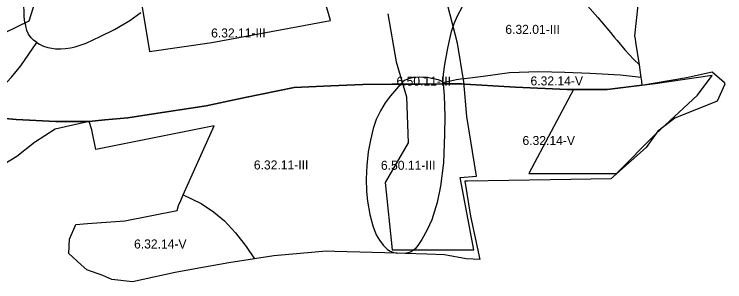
# Model space of a CAD drawing. Extents: x -555156 to -540209, y -1046851 to -1035695.
# Drawn here: x -542138 to -541353, y -1041203 to -1040907 of the extents above; entities that cross this region are included whole.
import ezdxf

# ---------------------------------------------------------------- set-up
doc = ezdxf.new("R2010")
doc.units = 0
for name, color, linetype in [('Vrstva 27', 7, 'Continuous'), ('Vrstva 28', 7, 'Continuous'), ('Vrstva 29', 7, 'Continuous')]:
    doc.layers.add(name, color=color, linetype=linetype)

msp = doc.modelspace()

# ---------------------------------------------------------------- linework, layer by layer
at = {"layer": 'Vrstva 28'}
for points in [[(-541451.53, -1040937.71), (-541452.1, -1040933.94), (-541452.57, -1040930.82), (-541447.15, -1040879.66), (-541446.57, -1040874.15), (-541476.12, -1040864.59), (-541481.08, -1040858.73), (-541481.64, -1040855.4), (-541482.26, -1040855.37), (-541485.3, -1040855.23), (-541482.64, -1040849.4), (-541483.84, -1040842.23), (-541503.49, -1040823.59)], [(-541568.84, -1040841.7), (-541562.46, -1040846.98), (-541560.17, -1040848.87), (-541557.04, -1040851.31), (-541548.08, -1040858.29), (-541535.08, -1040868.45), (-541523.28, -1040878.31), (-541520.69, -1040880.83), (-541512.08, -1040889.22), (-541505.13, -1040897.44), (-541493.63, -1040910.44), (-541479.44, -1040927.18), (-541475.39, -1040932.07), (-541472.3, -1040935.8), (-541463.64, -1040946.24), (-541454.38, -1040956.55), (-541447.73, -1040962.91)], [(-542113.35, -1040938.19), (-542117.02, -1040935.55), (-542119.58, -1040932.81), (-542122.48, -1040928.71), (-542124.27, -1040924.87), (-542125.49, -1040919.68), (-542125.55, -1040919.41), (-542125.78, -1040918.23), (-542126.75, -1040913.26), (-542127.13, -1040908.46), (-542127.43, -1040904.63), (-542127.52, -1040897.2), (-542127.79, -1040889.01)], [(-541664.64, -1040982.82), (-541664.47, -1040980.04), (-541664.34, -1040977.87), (-541664.12, -1040973.16), (-541662.76, -1040962.45), (-541659.19, -1040944.36), (-541657.55, -1040935.69), (-541655.16, -1040925.83), (-541652.47, -1040917.16), (-541648.73, -1040908.49), (-541643.25, -1040898.15)], [(-542113.35, -1040938.19), (-542110.36, -1040939.9), (-542105.92, -1040942.04), (-542101.23, -1040943.49), (-542096.87, -1040944.51), (-542092.52, -1040944.94), (-542087.46, -1040944.94), (-542086.89, -1040944.94), (-542081.43, -1040944.85), (-542076.13, -1040944), (-542070.76, -1040942.8), (-542058.95, -1040938.9), (-542043.26, -1040931.43), (-542027.43, -1040923.8), (-542010.55, -1040913.79), (-541998.45, -1040904.97)], [(-542199.52, -1041015.7), (-542198.76, -1041015.5), (-542190.86, -1041013.46), (-542183.84, -1041011.07), (-542173.68, -1041005.24), (-542162.63, -1040997.77), (-542151.42, -1040987.45), (-542141.41, -1040976.41), (-542130.95, -1040963.86), (-542113.35, -1040938.19)], [(-541447.73, -1040962.91), (-541451.53, -1040937.71)], [(-541445.64, -1040976.76), (-541447.73, -1040962.91)], [(-541445.64, -1040976.76), (-541468.79, -1040974.27), (-541501.99, -1040972.44), (-541530.22, -1040971.4), (-541558.97, -1040970.61), (-541591.12, -1040971.66), (-541620.14, -1040975.58), (-541640.88, -1040978.13), (-541645.09, -1040978.65), (-541649.94, -1040979.24), (-541653.03, -1040979.99), (-541664.64, -1040982.82)], [(-541664.42, -1040983.85), (-541644.02, -1040983.76), (-541640.69, -1040983.98), (-541584.67, -1040987.62), (-541527.56, -1040989.97), (-541483.23, -1040989.97), (-541478.55, -1040989.41), (-541447.75, -1040985.69), (-541395.74, -1040976.72), (-541367.24, -1040970.57)], [(-541367.24, -1040970.57), (-541354.03, -1040981.89)], [(-541664.64, -1040982.82), (-541664.88, -1040982.24), (-541665.22, -1040981.75), (-541665.65, -1040981.32), (-541666.22, -1040980.94), (-541666.87, -1040980.54), (-541667.86, -1040980.16), (-541668.14, -1040980.06), (-541669.62, -1040979.51), (-541671.77, -1040978.87), (-541674.39, -1040978.32), (-541677.34, -1040977.73), (-541680.35, -1040977.26), (-541683.33, -1040976.95), (-541686.63, -1040976.66), (-541690.73, -1040976.56), (-541694.58, -1040976.7), (-541697.46, -1040976.95), (-541702.39, -1040978.07), (-541704.39, -1040978.85), (-541706.58, -1040979.88), (-541707.04, -1040980.23), (-541709.02, -1040981.73), (-541711.53, -1040984.07)], [(-541444.98, -1040981.19), (-541445.44, -1040978.11), (-541445.64, -1040976.76)], [(-541711.53, -1040984.07), (-541720.74, -1040984.11), (-541753.03, -1040984.57), (-541788.51, -1040985.92), (-541829.15, -1040987.85), (-541883.28, -1040998.82), (-541905.62, -1041003.69), (-541926.36, -1041008.21), (-541989.22, -1041017.54), (-542012.92, -1041021.23), (-542038.14, -1041023.7), (-542055.32, -1041025.28), (-542092.44, -1041025.28), (-542136.24, -1041023.22), (-542144.14, -1041022.56), (-542165.98, -1041020.75), (-542194.83, -1041019.46), (-542212.55, -1041018.13)], [(-542055.32, -1041025.28), (-542038.14, -1041023.7), (-542012.92, -1041021.23), (-541989.22, -1041017.54), (-541926.36, -1041008.21), (-541905.62, -1041003.69), (-541883.28, -1040998.82), (-541829.15, -1040987.85), (-541788.51, -1040985.92), (-541753.03, -1040984.57), (-541720.74, -1040984.11), (-541711.7, -1040984.07)], [(-541711.7, -1040984.07), (-541722.57, -1040996.95)], [(-541711.7, -1040984.07), (-541694.54, -1040983.99), (-541689.55, -1040983.97), (-541664.42, -1040983.85)], [(-541694.54, -1040983.99), (-541711.53, -1040984.07)], [(-541354.03, -1040981.89), (-541353.36, -1040984.29), (-541361.62, -1041003.09), (-541408.5, -1041021.75), (-541427.29, -1041036.03), (-541440.19, -1041054.1), (-541479.13, -1041088.66), (-541523.26, -1041089.62), (-541637.49, -1041091.22), (-541640.39, -1041091.25), (-541634.14, -1041130.07), (-541624.03, -1041177.91), (-541639.01, -1041177.34), (-541662.96, -1041172.9), (-541682.57, -1041172.05), (-541706.3, -1041171.38)], [(-541664.54, -1040983.85), (-541689.55, -1040983.97), (-541694.54, -1040983.99)], [(-541664.54, -1040983.85), (-541664.58, -1040983.39), (-541664.64, -1040982.82)], [(-541444.5, -1040985.13), (-541447.75, -1040985.69), (-541483.23, -1040989.97), (-541527.56, -1040989.97), (-541584.67, -1040987.62), (-541640.69, -1040983.98), (-541644.02, -1040983.76), (-541664.54, -1040983.85)], [(-541664.42, -1040983.85), (-541663.5, -1040996.71)], [(-541444.5, -1040985.13), (-541444.98, -1040981.19)], [(-541722.57, -1040996.95), (-541728.34, -1041004.75), (-541733.64, -1041013.44), (-541738.3, -1041023.19), (-541741.69, -1041033.16), (-541744.66, -1041045.88), (-541747.42, -1041059.03), (-541748.9, -1041074.09), (-541749.32, -1041088.93), (-541749.11, -1041102.93), (-541748.05, -1041113.32), (-541745.3, -1041128.16), (-541742.12, -1041140.67), (-541738.3, -1041150.64), (-541734.62, -1041156.43), (-541730.63, -1041162.01), (-541725.9, -1041166.85), (-541723.07, -1041168.57), (-541719.95, -1041169.67), (-541715.34, -1041171.12)], [(-541663.5, -1040996.71), (-541662.65, -1041019.83), (-541662.86, -1041039.34), (-541664.17, -1041071.05), (-541667.56, -1041096.98), (-541671.19, -1041114.92), (-541676.88, -1041133.94), (-541681.97, -1041145.33), (-541688.12, -1041155.89), (-541692.41, -1041162.47), (-541695.18, -1041165.93), (-541697.53, -1041168.08), (-541699.61, -1041169.47), (-541701.96, -1041170.37), (-541706.3, -1041171.38)], [(-542212.55, -1041018.13), (-542194.83, -1041019.46), (-542165.98, -1041020.75), (-542144.14, -1041022.56), (-542136.24, -1041023.22), (-542092.44, -1041025.28), (-542055.32, -1041025.28)], [(-542055.32, -1041025.28), (-542092.96, -1041033.89), (-542115.94, -1041048.5), (-542135.22, -1041064.11), (-542155.58, -1041076.19), (-542180.4, -1041080.49), (-542186.41, -1041081.53), (-542189.29, -1041080.7), (-542208.88, -1041075.04), (-542212.45, -1041072.13), (-542214.58, -1041074), (-542265.94, -1041119.1)], [(-541951.6, -1041106.61), (-541917.4, -1041030.05), (-542048.17, -1041056.37), (-542052.52, -1041034.79), (-542055.32, -1041025.28)], [(-541872.93, -1041177.24), (-541901.29, -1041181.53), (-541938.52, -1041188.41), (-541960.56, -1041192.48), (-542007.74, -1041202.59), (-542030.47, -1041200.01), (-542040.4, -1041195.61), (-542057.88, -1041189.33), (-542064.19, -1041183.66), (-542077.75, -1041171.49), (-542077.14, -1041155.37), (-542070.07, -1041139.3), (-542057.41, -1041138.31), (-542016.19, -1041135.08), (-541958.29, -1041123.81), (-541956.86, -1041118.37), (-541954.37, -1041112.8), (-541951.6, -1041106.61)], [(-541951.6, -1041106.61), (-541931.89, -1041115.97)], [(-541931.89, -1041115.97), (-541918.12, -1041125.09), (-541906.04, -1041135.26), (-541893.75, -1041148.41), (-541881.88, -1041163.68), (-541872.93, -1041177.24)], [(-541715.34, -1041171.12), (-541784.14, -1041169.17), (-541793.49, -1041168.91), (-541851.32, -1041173.97), (-541872.93, -1041177.24)], [(-541706.3, -1041171.38), (-541715.34, -1041171.12)]]:
    msp.add_lwpolyline(points, dxfattribs=at)
at = {"layer": 'Vrstva 29'}
for points in [[(-542162.203006, -1040933.559002), (-542121.732003, -1040914.210991), (-542104.442995, -1040858.875009)], [(-541788.973022, -1040913.669983), (-541802.067993, -1040867.286011), (-541869.585022, -1040881.388977), (-541940.776978, -1040896.369995), (-541949.338989, -1040883.432007), (-541998.369995, -1040889.841003), (-541988.872009, -1040948.093994), (-541920.026978, -1040938.223022), (-541788.973022, -1040913.669983)], [(-541725.541009, -1040906.529007), (-541716.222001, -1040959.398007), (-541704.855007, -1040998.185994), (-541703.232, -1041048.939004), (-541728.490992, -1041092.933999), (-541720.727007, -1041167.089993), (-541630.721999, -1041167.187006), (-541645.768994, -1041087.128006), (-541627.72, -1041085.772996), (-541638.414003, -1041019.727005), (-541641.666996, -1040981.566994), (-541648.775008, -1040938.901002), (-541662.136999, -1040885.591991)], [(-541383.468018, -1040996.406006), (-541367.286011, -1040974.66803), (-541430.153015, -1040983.65802), (-541480.448975, -1040989.929993), (-541520.593994, -1040989.900024), (-541569.865906, -1041082.877991), (-541472.927002, -1041082.708008), (-541429.531982, -1041038.901001), (-541383.468018, -1040996.406006)]]:
    msp.add_lwpolyline(points, dxfattribs=at)

# ---------------------------------------------------------------- texts
at = {"layer": 'Vrstva 27'}
for s, p in [('6.32.11-III', (-541920.766548, -1040932.55)), ('6.32.01-III', (-541595.766548, -1040928.57)), ('6.50.11-III', (-541715.986548, -1040985.86)), ('6.32.14-V', (-541567.960884, -1040985.55)), ('6.32.14-V', (-541576.840884, -1041051.43)), ('6.32.11-III', (-541873.556548, -1041078.43)), ('6.50.11-III', (-541733.166548, -1041078.81)), ('6.32.14-V', (-542005.900884, -1041165.79))]:
    msp.add_text(s, height=10, dxfattribs=at).set_placement(p)

doc.saveas('drawing.dxf')
